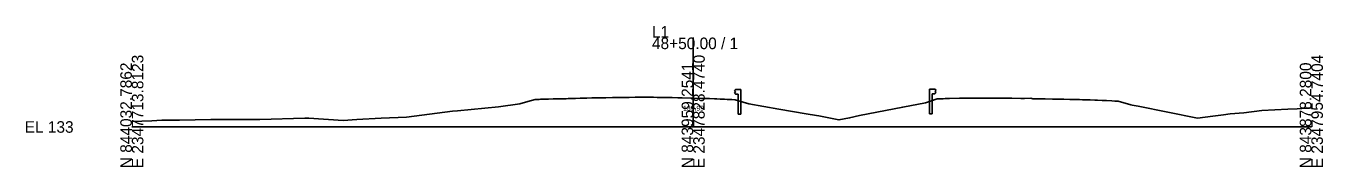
# Model space of a CAD drawing. Extents: x -26 to 2348258, y -10 to 844496.
# Drawn here: x 5143 to 5457.7, y 490.3 to 524.4 of the extents above; entities that cross this region are included whole.
import ezdxf

# ---------------------------------------------------------------- set-up
doc = ezdxf.new("R2010")
doc.units = 0
for name, color, linetype in [('Exist Cross Section Cell', 7, 'Continuous'), ('Exist XS Center Line Elevation Label', 7, 'Continuous'), ('Exist XS Ground Line', 7, 'Continuous'), ('Prop CMT Guardrail Graphics', 7, 'Continuous')]:
    doc.layers.add(name, color=color, linetype=linetype)

msp = doc.modelspace()

# ---------------------------------------------------------------- linework, layer by layer
at = {"layer": 'Exist Cross Section Cell'}
for p, q in [((5304.9, 500), (5304.9, 521.64)), ((5168.69, 500), (5304.9, 500)), ((5304.9, 500), (5454.9, 500))]:
    msp.add_line(p, q, dxfattribs=at)
at = {"layer": 'Exist XS Ground Line'}
msp.add_lwpolyline([(5168.69, 501.32), (5173.58, 501.5), (5175.97, 501.62), (5180.26, 501.68), (5187.85, 501.82), (5192.1, 501.83), (5199.73, 501.84), (5210.63, 502.1), (5211.23, 502.12), (5211.61, 502.1), (5219.93, 501.59), (5223.32, 501.78), (5229.15, 502.15), (5235.37, 502.41), (5246.5, 503.79), (5247.71, 503.93), (5257.69, 504.89), (5262.85, 505.56), (5264.76, 506.14), (5266.59, 506.63), (5267.5, 506.67), (5267.82, 506.69), (5268.63, 506.71), (5269.06, 506.73), (5269.8, 506.75), (5270.89, 506.78), (5271.55, 506.8), (5273.36, 506.83), (5274.07, 506.85), (5274.53, 506.86), (5276.31, 506.91), (5277.5, 506.94), (5278.13, 506.96), (5279.09, 506.98), (5280.28, 507.02), (5281.01, 507.03), (5282.73, 507.07), (5283.38, 507.09), (5283.71, 507.09), (5285.33, 507.12), (5286.36, 507.13), (5287.14, 507.15), (5288.36, 507.16), (5288.98, 507.17), (5289.37, 507.17), (5290.8, 507.19), (5292.34, 507.21), (5292.7, 507.21), (5293.36, 507.2), (5294.05, 507.2), (5295.27, 507.19), (5296.18, 507.17), (5297.56, 507.16), (5298.23, 507.15), (5299.79, 507.11), (5301.21, 507.08), (5302.25, 507.06), (5304.29, 507.01), (5304.88, 506.99), (5306.84, 506.93), (5307.16, 506.92), (5308.83, 506.86), (5310.09, 506.8), (5310.62, 506.78), (5311.45, 506.74), (5312.47, 506.7), (5313.12, 506.67), (5314.28, 506.62), (5315.12, 506.56), (5317.06, 506), (5318.38, 505.57), (5325.66, 504.32), (5332.29, 503.2), (5334.83, 502.76), (5335.36, 502.66), (5340.26, 501.69), (5342.85, 502.21), (5345.27, 502.79), (5355.74, 504.83), (5361.3, 505.83), (5362.49, 506.23), (5364.14, 506.79), (5365.56, 506.85), (5366.04, 506.86), (5367.06, 506.88), (5369.52, 506.94), (5370.37, 506.95), (5371.71, 506.97), (5372.57, 506.98), (5373.25, 506.99), (5374.58, 507), (5375.56, 507.01), (5376.39, 507.01), (5377.6, 507.01), (5378.41, 507), (5379.44, 506.99), (5381.42, 506.96), (5382.21, 506.95), (5384.39, 506.91), (5385.33, 506.92), (5386.81, 506.95), (5387.33, 506.85), (5388.47, 506.83), (5390.32, 506.8), (5392.09, 506.77), (5393.27, 506.74), (5394.83, 506.71), (5396.26, 506.67), (5397.48, 506.65), (5398.65, 506.62), (5399.38, 506.58), (5401.19, 506.53), (5402.34, 506.49), (5403.04, 506.46), (5404.18, 506.41), (5405.23, 506.37), (5406.52, 506.3), (5407.21, 506.24), (5408, 506.22), (5411.09, 505.38), (5411.42, 505.29), (5412.88, 505), (5427.29, 502.14), (5430.97, 502.58), (5433.58, 502.92), (5435.21, 503.18), (5438.48, 503.41), (5442.85, 503.98), (5449.21, 504.27), (5451.45, 504.41), (5454.9, 504.63)], dxfattribs=at)
at = {"layer": 'Prop CMT Guardrail Graphics'}
for p, q in [((5315.17, 509.08), (5314.9, 508.79)), ((5314.9, 508.79), (5315.17, 508.49)), ((5315.17, 508.49), (5314.9, 508.2)), ((5314.9, 508.2), (5315.17, 507.91)), ((5316.5, 509.08), (5315.17, 509.08)), ((5315.17, 507.91), (5315.84, 507.91)), ((5315.84, 507.91), (5315.84, 503.08)), ((5316.5, 503.08), (5316.5, 509.08)), ((5362.23, 503.19), (5362.23, 509.19)), ((5362.23, 509.19), (5363.56, 509.19)), ((5363.56, 508.02), (5362.89, 508.02)), ((5362.89, 508.02), (5362.89, 503.19)), ((5363.56, 509.19), (5363.83, 508.9)), ((5363.83, 508.9), (5363.56, 508.6)), ((5363.56, 508.6), (5363.83, 508.31)), ((5363.83, 508.31), (5363.56, 508.02)), ((5315.84, 503.08), (5316.5, 503.08)), ((5362.89, 503.19), (5362.23, 503.19))]:
    msp.add_line(p, q, dxfattribs=at)

# ---------------------------------------------------------------- texts
at = {"layer": 'Exist Cross Section Cell'}
for s, p in [('L1', (5294.9, 521.64)), ('48+50.00 / 1', (5294.9, 518.84)), ('EL 133', (5142.69, 498.6))]:
    msp.add_text(s, height=2.8, dxfattribs=at).set_placement(p)
for s, p in [('E 2347713.8123', (5171.49, 490)), ('E 2347828.4740', (5307.7, 490)), ('E 2347954.7404', (5457.7, 490)), ('N 844032.7862', (5168.69, 490)), ('N 843959.2541', (5304.9, 490)), ('N 843878.2800', (5454.9, 490))]:
    msp.add_text(s, height=2.8, rotation=90, dxfattribs=at).set_placement(p)
at = {"layer": 'Exist XS Center Line Elevation Label'}
msp.add_text('139.99', height=1.2, dxfattribs=at).set_placement((5302.45, 503.94))

doc.saveas('drawing.dxf')
